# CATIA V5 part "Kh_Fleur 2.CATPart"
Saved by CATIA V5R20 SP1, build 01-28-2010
Part number: Fleur 2
Bounding box of the stored display mesh (mm): x 0 to 20, y -33.167 to 33.167, z -30.751 to 33.99
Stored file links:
  G:\Khaled_CFAO_2011\SIL\SIL_GR1\tmerino\Khaled\CAD_Thinkmotion\Kh_Fleur 2.CATPart
  G:\Khaled_CFAO_2011\SIL\SIL_GR1\tmerino\Khaled\CAD_Thinkmotion\Kh_Catalog.CATMaterial
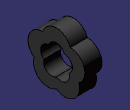
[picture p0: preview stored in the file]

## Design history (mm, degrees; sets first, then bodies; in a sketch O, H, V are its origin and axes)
Body1 (main body), material "Caoutchouc"
  Sketch1 on yz-plane, origin (0, 0, 0), H (0, 1, 0), V (0, 0, 1)
    arc A1 centre (0, 17) radius 17 from (16.168, 22.2533) to (-16.168, 22.2533) ccw
    point P2 (0, 0)
    arc A2 centre (-16.168, 5.2533) radius 17 from (-16.168, 22.2533) to (-26.1603, -8.5) ccw
    arc A3 centre (16.168, 5.2533) radius 17 from (26.1603, -8.5) to (16.168, 22.2533) ccw
    arc A4 centre (9.9923, -13.7533) radius 17 from (0, -27.5066) to (26.1603, -8.5) ccw
    arc A5 centre (-9.9923, -13.7533) radius 17 from (-26.1603, -8.5) to (0, -27.5066) ccw
    arc A6 centre (0, 9.5) radius 9.5 from (9.035, 12.4357) to (-9.035, 12.4357) ccw
    arc A7 centre (-9.035, 2.9357) radius 9.5 from (-9.035, 12.4357) to (-14.619, -4.75) ccw
    arc A8 centre (-5.584, -7.6857) radius 9.5 from (-14.619, -4.75) to (0, -15.3713) ccw
    arc A9 centre (9.035, 2.9357) radius 9.5 from (14.619, -4.75) to (9.035, 12.4357) ccw
    arc A10 centre (5.584, -7.6857) radius 9.5 from (0, -15.3713) to (14.619, -4.75) ccw
    distance A6 H = 0
  Pad1: profile Sketch1, direction (1, 0, 0), length 20
  Sketch2 on xy-plane, origin (0, 0, 0), H (1, 0, 0), V (0, 1, 0)
    axis line L1 (-10, 0) -> (40, 0)
    point P1 (-10, 0)
    coincidence: P1 H
    horizontal: L1 H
